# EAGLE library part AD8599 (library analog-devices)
Single and Dual, Ultralow Distortion, Ultralow Noise Op Amps Source: http://www.analog.com/static/imported-files/data_sheets/AD8597_8599.pdf
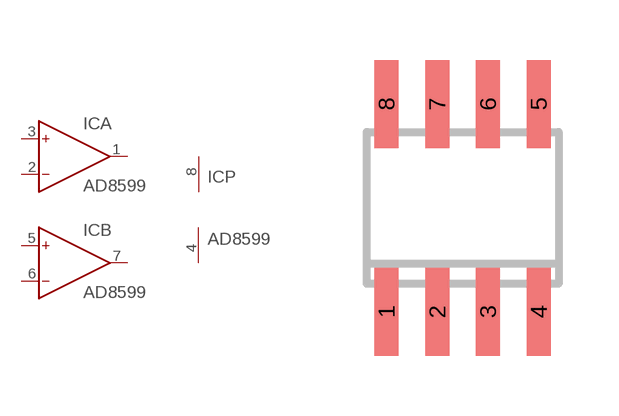
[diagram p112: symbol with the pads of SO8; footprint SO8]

Designator prefix IC; gates A=OP B=OP P=PWR+-

## AD8599R (MPN: AD8599ARZ; OC_FARNELL: 1438872; OC_NEWARK: 34M5072)  [SO8]
1  A:OUT  out
2  A:IN-  in
3  A:IN+  in
4  P:V-  pwr
5  B:IN+  in
6  B:IN-  in
7  B:OUT  out
8  P:V+  pwr

## Footprint SO8 (pad centres in mm)
8-Lead Small Outline IC (SO-8) Source: http://www.analog.com/UploadedFiles/Data_Sheets/703465986AD8611_2_0.pdf
smd 0.6 x 2.2: 1 -1.905,-2.6; 2 -0.635,-2.6; 3 0.635,-2.6; 4 1.905,-2.6; 5 1.905,2.6; 6 0.635,2.6; 7 -0.635,2.6; 8 -1.905,2.6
